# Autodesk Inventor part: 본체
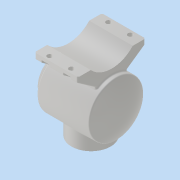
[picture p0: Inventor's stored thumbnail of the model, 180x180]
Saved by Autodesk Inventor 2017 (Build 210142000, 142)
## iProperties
Part Number: 본체
Material: 알루미늄 6061
Document SubType Name: Modeling
Designer: MRC
Density: 2.7 g/cm^3
Appearance: 알루미늄 - 평지
Mass: 1296.71 g
Surface Area: 1060.44 cm^2
Volume: 480.264 cm^3
Author: MRC
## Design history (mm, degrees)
sketch "스케치1"
  geometry: L1 (-62, 0)-(58, 0); L2 (41.887, 43)-(-43, 43); L3 (-43, 43)-(-43, 27); L4 (-43, 27)-(-62, 27); L5 (-62, 27)-(-62, 36); L6 (-62, 36)-(-50, 36); L7 (-50, 36)-(-50, 50); L8 (-50, 50)-(46.336, 50); A1 r 106 centre (-55, 0) between (51, 0) and (41.887, 43); A2 r 113 centre (-55, 0) between (58, 0) and (46.336, 50); 1 further point
  constraints: 16 end point, 4 perpendicular, 4 point on circle, 3 horizontal, 3 point on line, 2 centre point, 1 coincident, 1 vertical, 1 vertical alignment
  dimensions: "d6" = 120 distance of L1.end L1.start; "d7" = 62 distance of point (0, 0) L1.start; "d8" = 72 diameter of L6 L1; "d9" = 54 diameter of L4 L1; "d10" = 100 diameter of L8 L1; "d11" = 86 diameter of L2 L1; "d12" = 113 radius of A2; "d14" = 7 radial gap between concentric circles of A2 A1; "d24" = 19 distance of L3.end L4.end; "d25" = 108 distance from line of L7 L1.end
revolve "회전1" sketch "스케치1" stored, may be unused: angle "d15" = 90 deg
node "작업 평면1"
sketch "스케치2"
  geometry: C1 r 36 at (0, 0); 1 further point
  constraints: 1 centre point, 1 coincident
  dimensions: "d17" = 72 diameter of C1
extrude "돌출1" join sketch "스케치2" stored distance "d18" = 10; taper "d19" = 0 deg
node "작업 평면2"
sketch "스케치3"
  geometry: L1 (26.694, 42.278)-(62, 67); L2 (62, 67)-(62, 77); L3 (62, 77)-(38.5, 77); L4 (-26.694, 42.278)-(-62, 67); L5 (-62, 67)-(-62, 77); L6 (-62, 77)-(-38.5, 77); A1 r 50 centre (0, 0) between (26.694, 42.278) and (-26.694, 42.278) reference; A2 r 52.096 centre (0, 112.096) between (-38.5, 77) and (38.5, 77); 1 further point
  constraints: 12 end point, 4 point on circle, 2 equal length, 2 vertical, 1 centre point, 1 collinear, 1 horizontal, 1 perpendicular, 1 vertical alignment
  dimensions: "d26" = 77 distance of L6.end L3.end; "d27" = 77 distance from line of L6 point (0, 0); "d28" = 124 distance between parallel lines of L5 L2; "d29" = 17 distance edge to line of A2 L6; "d30" = 10 distance of L4.end L5.end; "d31" = 55 deg angle of L4 L5; "d32" = 55 deg angle of L1 L2
extrude "돌출2" join sketch "스케치3" distance "d33" = 80; taper "d34" = 0 deg
sketch "스케치4"
  geometry: L1 (0, 0)-(0, 23.5) reference; C1 r 4.5 at (20, 8); 1 further point
  constraints: 1 centre point
  dimensions: "d35" = 54 vertical distance of point (42, 62) C1.centre; "d37" = 9 diameter of C1; "d92" = 20 distance from line of L1 C1.centre
extrude "돌출3" cut sketch "스케치4" distance "d38" = 6; taper "d39" = 0 deg
sketch "스케치5"
  geometry: L1 (7, 0)-(7, -8); L2 (-20, -8)-(60, -8) reference; L3 (-7, 0)-(-7, -8); A1 r 7 centre (0, 0) between (7, 0) and (-7, 0); 1 further point
  constraints: 4 end point, 2 point on circle, 2 point on line, 1 centre point, 1 parallel, 1 perpendicular, 1 tangent
  dimensions: "d46" = 14 diameter of A1
extrude "돌출4" cut sketch "스케치5" stored distance "d47" = 6; taper "d48" = 0 deg
sketch "스케치6"
  geometry: C1 r 27 at (0, 0); 1 further point
  constraints: 1 centre point, 1 coincident
  dimensions: "d52" = 54 diameter of C1
extrude "돌출5" cut sketch "스케치6" stored distance "d53" = 6; taper "d54" = 0 deg
sketch "스케치7"
  geometry: 2 further points
  dimensions: "d55" = 32.5 distance of point (0, 0) point (-32.5, 0)
hole "구멍1" sketch "스케치7" at (-32.5, 0) diameter "d56" = 3.242; stored, may be unused: countersink angle "d60" = 90 deg, drill point angle "d62" = 118 deg; dims "d57" = 8, "d58" = 4, "d59" = 2, "d61" = 10
sketch "스케치8"
  geometry: 2 further points
  dimensions: "d66" = 32.5 distance of point (0, 0) point (-32.5, 0)
hole "구멍2" sketch "스케치8" at (-32.5, 0) diameter "d67" = 3.242; stored, may be unused: countersink angle "d71" = 90 deg, drill point angle "d73" = 118 deg; dims "d68" = 8, "d69" = 4, "d70" = 2, "d72" = 10
fillet "모깎기1" dims "d81" = 3
fillet "모깎기2" dims "d82" = 3
fillet "모깎기3" dims "d83" = 3
fillet "모깎기4" dims "d84" = 3
chamfer "모따기1" distance "d85" = 1; stored, may be unused: second distance "d86" = 2, angle "d87" = 45 deg
node "작업 평면7"
sketch "스케치10"
  geometry: L1 (62, 36)-(62, -36) reference; 2 further points
  constraints: 1 coincident, 1 other
  dimensions: "d89" = 62 distance from line of L1 point (0, 0)
feature "엠보싱1" sketch "스케치10" dims "d6" = 120, "d7" = 62, "d8" = 72, "d9" = 54, "d10" = 100, "d11" = 86, "d12" = 113, "d14" = 7, "d24" = 19, "d25" = 108, "d90" = 0.5, "d91" = 0
fillet "모깎기5" dims "d93" = 3
node "솔리드1"
pattern_linear "직사각형 패턴1" dims "d42" = 108, "d45" = 40
pattern_linear "직사각형 패턴2" dims "d51" = 40
mirror "미러1"
pattern_circular "원형 패턴1" dims angle "d64" = 360 deg
pattern_circular "원형 패턴2" dims angle "d75" = 360 deg
other parameters: "d16" = -65, "d20" = -42
